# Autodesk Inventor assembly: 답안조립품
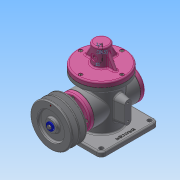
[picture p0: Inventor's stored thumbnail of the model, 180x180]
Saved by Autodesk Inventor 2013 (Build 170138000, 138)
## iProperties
Created: 2020-02
Part Number: 답안조립품
Document SubType Name: Assembly
Designer: Administrator
Mass: 2563.01 g
Surface Area: 2485.59 cm^2
Volume: 789.814 cm^3
Density: 3.24508 g/cm^3
Author: Administrator
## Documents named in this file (21)
- C:\Users\Administrator\Desktop\600206V1003\답안조립품.iam
- C:\Users\Administrator\Desktop\600206V1003\본체.ipt
- C:\Users\Administrator\Desktop\600206V1003\19가변스프링.ipt
- C:\Users\Administrator\Desktop\600206V1003\E-링.ipt
- C:\Users\Administrator\Desktop\600206V1003\Ű 4 x 4 x 25.ipt
- C:\Users\Administrator\Desktop\600206V1003\V-벨트풀리.ipt
- C:\Users\Administrator\Desktop\600206V1003\개스킷 A.ipt
- C:\Users\Administrator\Desktop\600206V1003\개스킷 B.ipt
- C:\Users\Administrator\Desktop\600206V1003\덮개.ipt
- C:\Users\Administrator\Desktop\600206V1003\뒤커버.ipt
- C:\Users\Administrator\Desktop\600206V1003\링크.ipt
- C:\Users\Administrator\Desktop\600206V1003\베어링 17 x 40 x 12.ipt
- C:\Users\Administrator\Desktop\600206V1003\볼트 M4 x 10.ipt
- C:\Users\Administrator\Desktop\600206V1003\슬라이더.ipt
- C:\Users\Administrator\Desktop\600206V1003\앞커버.ipt
- C:\Users\Administrator\Desktop\600206V1003\오일 실 17 30 8.ipt
- C:\Users\Administrator\Desktop\600206V1003\와셔 4x16.ipt
- C:\Users\Administrator\Desktop\600206V1003\육각 소켓 머리 볼트 M4 x 10.ipt
- C:\Users\Administrator\Desktop\600206V1003\클레비스 핀 6 x 22.ipt
- 클레비스 핀 6 x 22.ipt
- C:\Users\Administrator\Desktop\600206V1003\편심축.ipt
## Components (7 placed, 6 different names)
1. 19가변스프링:1
2. E-링:1
3. Ű 4 x 4 x 25:1
4. V-벨트풀리:1
5. 개스킷 A:1
6. 개스킷 B:1
7. 개스킷 A:2
